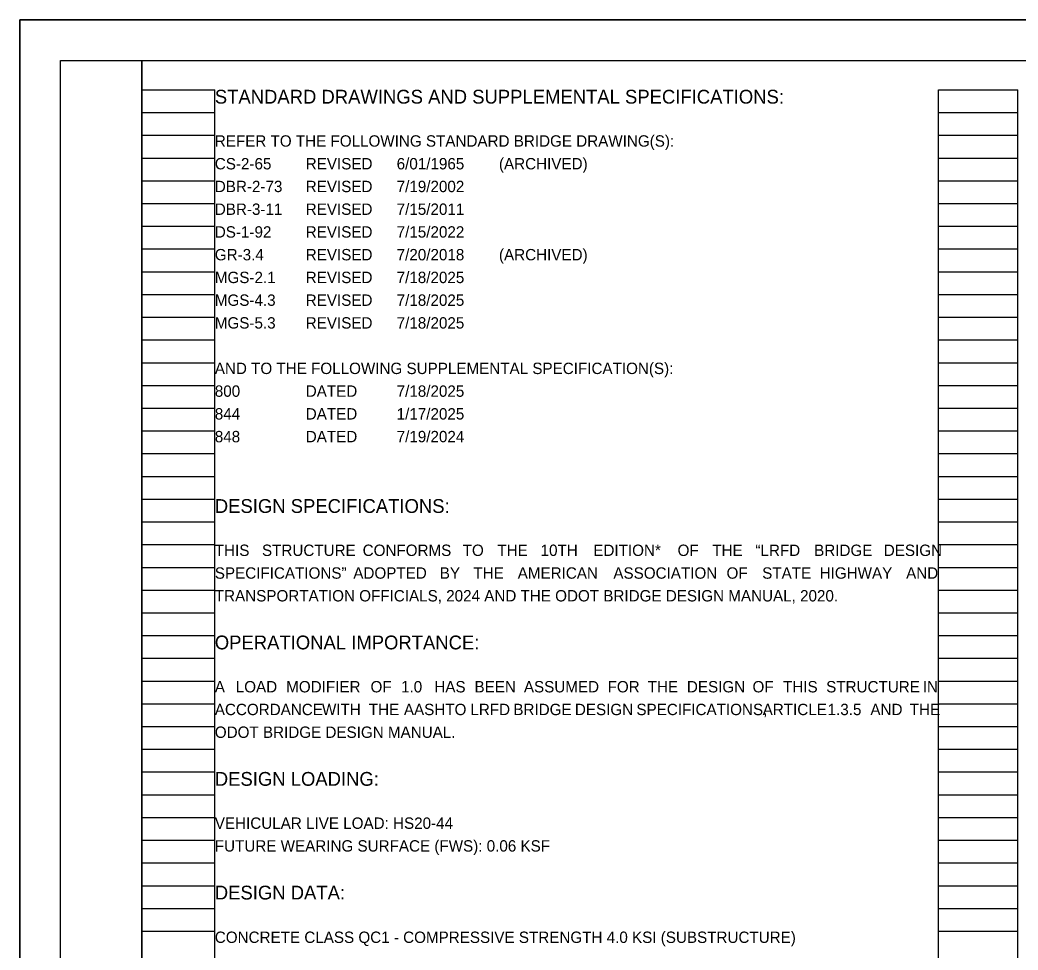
# Model space of a CAD drawing. Extents: x 0 to 44.4, y -4.7 to 22.
# Drawn here: x 0 to 12.29, y 10.55 to 22 of the extents above; entities that cross this region are included whole.
import ezdxf

# ---------------------------------------------------------------- set-up
doc = ezdxf.new("R2010")
doc.units = 0
for name, color, linetype in [('SC_Scratch1', 7, 'Continuous'), ('SH_Border', 7, 'Continuous'), ('SH_Cut_Line', 7, 'Continuous'), ('SH_Text', 7, 'Continuous')]:
    doc.layers.add(name, color=color, linetype=linetype)

msp = doc.modelspace()

# ---------------------------------------------------------------- linework, layer by layer
at = {"layer": 'SC_Scratch1'}
for p, q in [((1.5, 0.98), (1.5, 21.14)), ((1.5, 21.14), (2.4, 21.14)), ((2.4, 0.98), (2.4, 21.14)), ((11.313, 0.98), (11.313, 21.14)), ((11.313, 21.14), (12.293, 21.14)), ((12.293, 0.98), (12.293, 21.14)), ((1.5, 20.86), (2.4, 20.86)), ((11.313, 20.86), (12.293, 20.86)), ((1.5, 20.58), (2.4, 20.58)), ((11.313, 20.58), (12.293, 20.58)), ((1.5, 20.3), (2.4, 20.3)), ((11.313, 20.3), (12.293, 20.3)), ((1.5, 20.02), (2.4, 20.02)), ((11.313, 20.02), (12.293, 20.02)), ((1.5, 19.74), (2.4, 19.74)), ((11.313, 19.74), (12.293, 19.74)), ((1.5, 19.46), (2.4, 19.46)), ((11.313, 19.46), (12.293, 19.46)), ((1.5, 19.18), (2.4, 19.18)), ((11.313, 19.18), (12.293, 19.18)), ((1.5, 18.9), (2.4, 18.9)), ((11.313, 18.9), (12.293, 18.9)), ((1.5, 18.62), (2.4, 18.62)), ((11.313, 18.62), (12.293, 18.62)), ((1.5, 18.34), (2.4, 18.34)), ((11.313, 18.34), (12.293, 18.34)), ((1.5, 18.06), (2.4, 18.06)), ((11.313, 18.06), (12.293, 18.06)), ((1.5, 17.78), (2.4, 17.78)), ((11.313, 17.78), (12.293, 17.78)), ((1.5, 17.5), (2.4, 17.5)), ((11.313, 17.5), (12.293, 17.5)), ((1.5, 17.22), (2.4, 17.22)), ((11.313, 17.22), (12.293, 17.22)), ((1.5, 16.94), (2.4, 16.94)), ((11.313, 16.94), (12.293, 16.94)), ((1.5, 16.66), (2.4, 16.66)), ((11.313, 16.66), (12.293, 16.66)), ((1.5, 16.38), (2.4, 16.38)), ((11.313, 16.38), (12.293, 16.38)), ((1.5, 16.1), (2.4, 16.1)), ((11.313, 16.1), (12.293, 16.1)), ((1.5, 15.82), (2.4, 15.82)), ((11.313, 15.82), (12.293, 15.82)), ((1.5, 15.54), (2.4, 15.54)), ((11.313, 15.54), (12.293, 15.54)), ((1.5, 15.26), (2.4, 15.26)), ((11.313, 15.26), (12.293, 15.26)), ((1.5, 14.98), (2.4, 14.98)), ((11.313, 14.98), (12.293, 14.98)), ((1.5, 14.7), (2.4, 14.7)), ((11.313, 14.7), (12.293, 14.7)), ((1.5, 14.42), (2.4, 14.42)), ((11.313, 14.42), (12.293, 14.42)), ((1.5, 14.14), (2.4, 14.14)), ((11.313, 14.14), (12.293, 14.14)), ((1.5, 13.86), (2.4, 13.86)), ((11.313, 13.86), (12.293, 13.86)), ((1.5, 13.58), (2.4, 13.58)), ((11.313, 13.58), (12.293, 13.58)), ((1.5, 13.3), (2.4, 13.3)), ((11.313, 13.3), (12.293, 13.3)), ((1.5, 13.02), (2.4, 13.02)), ((11.313, 13.02), (12.293, 13.02)), ((1.5, 12.74), (2.4, 12.74)), ((11.313, 12.74), (12.293, 12.74)), ((1.5, 12.46), (2.4, 12.46)), ((11.313, 12.46), (12.293, 12.46)), ((1.5, 12.18), (2.4, 12.18)), ((11.313, 12.18), (12.293, 12.18)), ((1.5, 11.9), (2.4, 11.9)), ((11.313, 11.9), (12.293, 11.9)), ((1.5, 11.62), (2.4, 11.62)), ((11.313, 11.62), (12.293, 11.62)), ((1.5, 11.34), (2.4, 11.34)), ((11.313, 11.34), (12.293, 11.34)), ((1.5, 11.06), (2.4, 11.06)), ((11.313, 11.06), (12.293, 11.06)), ((1.5, 10.78), (2.4, 10.78)), ((11.313, 10.78), (12.293, 10.78))]:
    msp.add_line(p, q, dxfattribs=at)
msp.add_lwpolyline([(0, 22), (34, 22), (34, 0), (0, 0)], close=True, dxfattribs=at)
at = {"layer": 'SH_Border'}
for points in [[(0.5, 21.5), (1.5, 21.5), (1.5, 0.5), (0.5, 0.5)], [(1.5, 21.5), (33.5, 21.5), (33.5, 0.5), (1.5, 0.5)]]:
    msp.add_lwpolyline(points, close=True, dxfattribs=at)
at = {"layer": 'SH_Cut_Line'}
msp.add_lwpolyline([(0, 0), (34, 0), (34, 22), (0, 22)], close=True, dxfattribs=at)

# ---------------------------------------------------------------- texts
at = {"layer": 'SH_Text'}
for s, height, p in [('STANDARD DRAWINGS AND SUPPLEMENTAL SPECIFICATIONS:', 0.17, (2.4, 20.97)), ('REFER TO THE FOLLOWING STANDARD BRIDGE DRAWING(S):', 0.14, (2.4, 20.44)), ('CS-2-65', 0.14, (2.4, 20.16)), ('REVISED', 0.14, (3.52, 20.16)), ('6/01/1965', 0.14, (4.64, 20.16)), ('(ARCHIVED)', 0.14, (5.9, 20.16)), ('DBR-2-73', 0.14, (2.4, 19.88)), ('REVISED', 0.14, (3.52, 19.88)), ('7/19/2002', 0.14, (4.64, 19.88)), ('DBR-3-11', 0.14, (2.4, 19.6)), ('REVISED', 0.14, (3.52, 19.6)), ('7/15/2011', 0.14, (4.64, 19.6)), ('DS-1-92 ', 0.14, (2.4, 19.32)), ('REVISED', 0.14, (3.52, 19.32)), ('7/15/2022', 0.14, (4.64, 19.32)), ('GR-3.4', 0.14, (2.4, 19.04)), ('REVISED', 0.14, (3.52, 19.04)), ('7/20/2018', 0.14, (4.64, 19.04)), ('(ARCHIVED)', 0.14, (5.9, 19.04)), ('MGS-2.1', 0.14, (2.4, 18.76)), ('REVISED', 0.14, (3.52, 18.76)), ('7/18/2025', 0.14, (4.64, 18.76)), ('MGS-4.3', 0.14, (2.4, 18.48)), ('REVISED', 0.14, (3.52, 18.48)), ('7/18/2025', 0.14, (4.64, 18.48)), ('MGS-5.3', 0.14, (2.4, 18.2)), ('REVISED', 0.14, (3.52, 18.2)), ('7/18/2025', 0.14, (4.64, 18.2)), ('AND TO THE FOLLOWING SUPPLEMENTAL SPECIFICATION(S):', 0.14, (2.4, 17.64)), ('800', 0.14, (2.4, 17.36)), ('DATED', 0.14, (3.52, 17.36)), ('7/18/2025', 0.14, (4.64, 17.36)), ('844', 0.14, (2.4, 17.08)), ('DATED', 0.14, (3.52, 17.08)), ('1/17/2025', 0.14, (4.64, 17.08)), ('848', 0.14, (2.4, 16.8)), ('DATED', 0.14, (3.52, 16.8)), ('7/19/2024', 0.14, (4.64, 16.8)), ('DESIGN SPECIFICATIONS:', 0.17, (2.4, 15.93)), ('THIS ', 0.14, (2.4, 15.4)), ('STRUCTURE ', 0.14, (2.981, 15.4)), ('CONFORMS ', 0.14, (4.221, 15.4)), ('TO ', 0.14, (5.453, 15.4)), ('THE ', 0.14, (5.88, 15.4)), ('10TH ', 0.14, (6.413, 15.4)), ('EDITION* ', 0.14, (7.062, 15.4)), ('OF ', 0.14, (8.1, 15.4)), ('THE ', 0.14, (8.527, 15.4)), ('“LRFD ', 0.14, (9.059, 15.4)), ('BRIDGE ', 0.14, (9.782, 15.4)), ('DESIGN ', 0.14, (10.64, 15.4)), ('SPECIFICATIONS” ', 0.14, (2.4, 15.12)), ('ADOPTED ', 0.14, (4.106, 15.12)), ('BY ', 0.14, (5.171, 15.12)), ('THE ', 0.14, (5.585, 15.12)), ('AMERICAN ', 0.14, (6.131, 15.12)), ('ASSOCIATION ', 0.14, (7.309, 15.12)), ('OF ', 0.14, (8.703, 15.12)), ('STATE ', 0.14, (9.142, 15.12)), ('HIGHWAY ', 0.14, (9.85, 15.12)), ('AND ', 0.14, (10.915, 15.12)), ('TRANSPORTATION OFFICIALS, 2024 AND THE ODOT BRIDGE DESIGN MANUAL, 2020.', 0.14, (2.4, 14.84)), ('OPERATIONAL IMPORTANCE:', 0.17, (2.4, 14.25)), ('A ', 0.14, (2.4, 13.72)), ('LOAD ', 0.14, (2.658, 13.72)), ('MODIFIER ', 0.14, (3.279, 13.72)), ('OF ', 0.14, (4.318, 13.72)), ('1.0 ', 0.14, (4.694, 13.72)), ('HAS ', 0.14, (5.104, 13.72)), ('BEEN ', 0.14, (5.599, 13.72)), ('ASSUMED ', 0.14, (6.207, 13.72)), ('FOR ', 0.14, (7.238, 13.72)), ('THE ', 0.14, (7.732, 13.72)), ('DESIGN ', 0.14, (8.215, 13.72)), ('OF ', 0.14, (9.023, 13.72)), ('THIS ', 0.14, (9.399, 13.72)), ('STRUCTURE ', 0.14, (9.93, 13.72)), ('IN ', 0.14, (11.12, 13.72)), ('ACCORDANCE ', 0.14, (2.4, 13.44)), ('WITH ', 0.14, (3.72, 13.44)), ('THE ', 0.14, (4.297, 13.44)), ('AASHTO ', 0.14, (4.729, 13.44)), ('LRFD ', 0.14, (5.548, 13.44)), ('BRIDGE ', 0.14, (6.077, 13.44)), ('DESIGN ', 0.14, (6.835, 13.44)), ('SPECIFICATIONS, ', 0.14, (7.593, 13.44)), ('ARTICLE ', 0.14, (9.148, 13.44)), ('1.3.5 ', 0.14, (9.948, 13.44)), ('AND ', 0.14, (10.475, 13.44)), ('THE ', 0.14, (10.96, 13.44)), ('ODOT BRIDGE DESIGN MANUAL.', 0.14, (2.4, 13.16)), ('DESIGN LOADING:', 0.17, (2.4, 12.57)), ('VEHICULAR LIVE LOAD: HS20-44', 0.14, (2.4, 12.04)), ('FUTURE WEARING SURFACE (FWS): 0.06 KSF', 0.14, (2.4, 11.76)), ('DESIGN DATA:', 0.17, (2.4, 11.17)), ('CONCRETE CLASS QC1 - COMPRESSIVE STRENGTH 4.0 KSI (SUBSTRUCTURE)', 0.14, (2.4, 10.635))]:
    msp.add_text(s, height=height, dxfattribs=at).set_placement(p)

doc.saveas('drawing.dxf')
